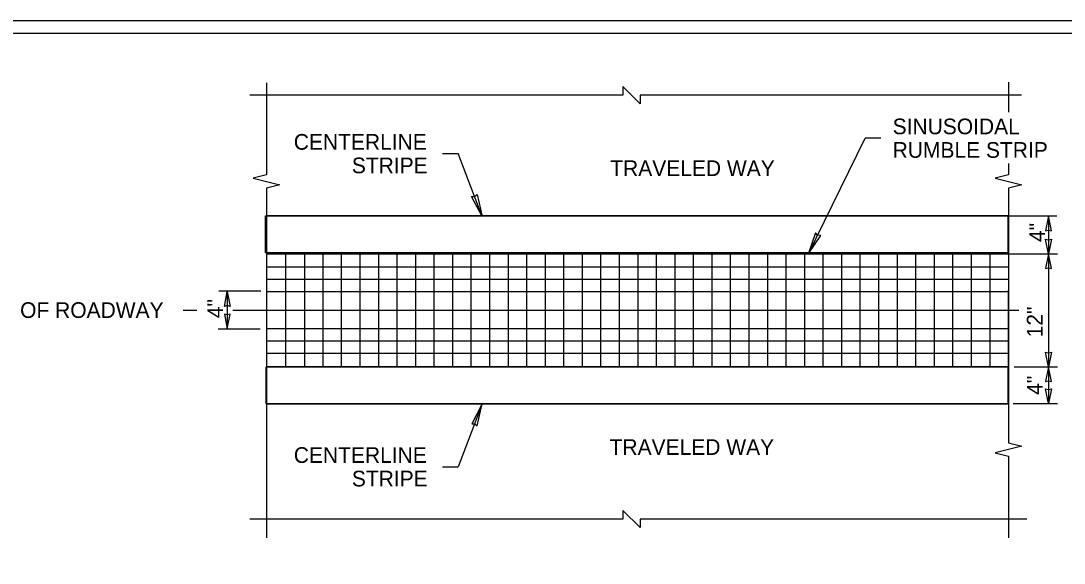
# Model space of a CAD drawing. Extents: x 100019.3 to 100035.8, y 99999.9 to 100024.4.
# Drawn here: x 100024.46 to 100029.77, y 100021.67 to 100024.44 of the extents above; entities that cross this region are included whole.
import ezdxf

# ---------------------------------------------------------------- set-up
doc = ezdxf.new("R2010")
doc.units = 0
for name, color, linetype in [('Level 10', 7, 'Continuous'), ('Level 14', 7, 'Continuous'), ('Level 15', 7, 'Continuous'), ('Level 16', 7, 'Continuous'), ('Level 18', 7, 'Continuous'), ('Level 20', 7, 'Continuous'), ('Level 22', 7, 'Continuous'), ('Level 45', 7, 'Continuous'), ('Level 50', 7, 'Continuous'), ('SH_GI_PlotLimits', 7, 'Continuous'), ('SH_GI_SheetBorder', 7, 'Continuous')]:
    doc.layers.add(name, color=color, linetype=linetype)

msp = doc.modelspace()

# ---------------------------------------------------------------- linework, layer by layer
at = {"layer": 'Level 10'}
for p, q in [((100025.8077, 100022.6793), (100025.8077, 100023.2455)), ((100025.9037, 100022.6793), (100025.9037, 100023.2455)), ((100025.9977, 100022.6793), (100025.9977, 100023.2455)), ((100026.0921, 100023.0648), (100026.0921, 100023.2455)), ((100026.1865, 100023.0648), (100026.1865, 100023.2455)), ((100026.2808, 100023.0648), (100026.2808, 100023.2455)), ((100026.3752, 100023.0648), (100026.3752, 100023.2455)), ((100026.4696, 100023.0648), (100026.4696, 100023.2455)), ((100026.564, 100023.0648), (100026.564, 100023.2455)), ((100026.6583, 100023.0648), (100026.6583, 100023.2455)), ((100026.7527, 100022.6793), (100026.7527, 100023.2455)), ((100026.8471, 100023.0648), (100026.8471, 100023.2455)), ((100026.9414, 100023.0648), (100026.9414, 100023.2455)), ((100027.0358, 100023.0648), (100027.0358, 100023.2455)), ((100027.1302, 100023.0648), (100027.1302, 100023.2455)), ((100027.2246, 100023.0648), (100027.2246, 100023.2455)), ((100027.3189, 100023.0648), (100027.3189, 100023.2455)), ((100027.4133, 100023.0648), (100027.4133, 100023.2455)), ((100027.5077, 100022.6793), (100027.5077, 100023.2455)), ((100027.602, 100023.0648), (100027.602, 100023.2455)), ((100027.6964, 100023.0648), (100027.6964, 100023.2455)), ((100027.7908, 100023.0648), (100027.7908, 100023.2455)), ((100027.8852, 100023.0648), (100027.8852, 100023.2455)), ((100027.9795, 100023.0648), (100027.9795, 100023.2455)), ((100028.0739, 100023.0648), (100028.0739, 100023.2455)), ((100028.1683, 100023.0648), (100028.1683, 100023.2455)), ((100028.2626, 100022.6793), (100028.2626, 100023.2455)), ((100028.357, 100023.0648), (100028.357, 100023.2455)), ((100028.4514, 100023.0648), (100028.4514, 100023.2455)), ((100028.5458, 100023.0648), (100028.5458, 100023.2455)), ((100028.6401, 100023.0648), (100028.6401, 100023.2455)), ((100028.7345, 100023.0648), (100028.7345, 100023.2455)), ((100028.8289, 100023.0648), (100028.8289, 100023.2455)), ((100028.9232, 100023.0648), (100028.9232, 100023.2455)), ((100029.0176, 100022.6793), (100029.0176, 100023.2455)), ((100029.112, 100023.0648), (100029.112, 100023.2455)), ((100029.2064, 100023.0648), (100029.2064, 100023.2455)), ((100029.3007, 100023.0648), (100029.3007, 100023.2455)), ((100029.3951, 100023.2455), (100029.3951, 100023.0648)), ((100026.0921, 100022.8492), (100026.0921, 100023.0648)), ((100026.1865, 100022.8492), (100026.1865, 100023.0648)), ((100026.2808, 100022.8492), (100026.2808, 100023.0648)), ((100026.3752, 100022.8492), (100026.3752, 100023.0648)), ((100026.4696, 100022.8492), (100026.4696, 100023.0648)), ((100026.564, 100022.8492), (100026.564, 100023.0648)), ((100026.6583, 100022.8492), (100026.6583, 100023.0648)), ((100026.8471, 100022.8492), (100026.8471, 100023.0648)), ((100026.9414, 100022.8492), (100026.9414, 100023.0648)), ((100027.0358, 100022.8492), (100027.0358, 100023.0648)), ((100027.1302, 100022.8492), (100027.1302, 100023.0648)), ((100027.2246, 100022.8492), (100027.2246, 100023.0648)), ((100027.3189, 100022.8492), (100027.3189, 100023.0648)), ((100027.4133, 100022.8492), (100027.4133, 100023.0648)), ((100027.602, 100022.8492), (100027.602, 100023.0648)), ((100027.6964, 100022.8492), (100027.6964, 100023.0648)), ((100027.7908, 100022.8492), (100027.7908, 100023.0648)), ((100027.8852, 100022.8492), (100027.8852, 100023.0648)), ((100027.9795, 100022.8492), (100027.9795, 100023.0648)), ((100028.0739, 100022.8492), (100028.0739, 100023.0648)), ((100028.1683, 100022.8492), (100028.1683, 100023.0648)), ((100028.357, 100022.8492), (100028.357, 100023.0648)), ((100028.4514, 100022.8492), (100028.4514, 100023.0648)), ((100028.5458, 100022.8492), (100028.5458, 100023.0648)), ((100028.6401, 100022.8492), (100028.6401, 100023.0648)), ((100028.7345, 100022.8492), (100028.7345, 100023.0648)), ((100028.8289, 100022.8492), (100028.8289, 100023.0648)), ((100028.9232, 100022.8492), (100028.9232, 100023.0648)), ((100029.112, 100022.8492), (100029.112, 100023.0648)), ((100029.2064, 100022.8492), (100029.2064, 100023.0648)), ((100029.3007, 100022.8492), (100029.3007, 100023.0648)), ((100029.3951, 100023.0648), (100029.3951, 100022.8492)), ((100029.4895, 100022.8492), (100029.4895, 100023.0648)), ((100026.0921, 100022.6793), (100026.0921, 100022.8492)), ((100026.1865, 100022.6793), (100026.1865, 100022.8492)), ((100026.2808, 100022.6793), (100026.2808, 100022.8492)), ((100026.3752, 100022.6793), (100026.3752, 100022.8492)), ((100026.4696, 100022.6793), (100026.4696, 100022.8492)), ((100026.564, 100022.6793), (100026.564, 100022.8492)), ((100026.6583, 100022.6793), (100026.6583, 100022.8492)), ((100026.8471, 100022.6793), (100026.8471, 100022.8492)), ((100026.9414, 100022.6793), (100026.9414, 100022.8492)), ((100027.0358, 100022.6793), (100027.0358, 100022.8492)), ((100027.1302, 100022.6793), (100027.1302, 100022.8492)), ((100027.2246, 100022.6793), (100027.2246, 100022.8492)), ((100027.3189, 100022.6793), (100027.3189, 100022.8492)), ((100027.4133, 100022.6793), (100027.4133, 100022.8492)), ((100027.602, 100022.6793), (100027.602, 100022.8492)), ((100027.6964, 100022.6793), (100027.6964, 100022.8492)), ((100027.7908, 100022.6793), (100027.7908, 100022.8492)), ((100027.8852, 100022.6793), (100027.8852, 100022.8492)), ((100027.9795, 100022.6793), (100027.9795, 100022.8492)), ((100028.0739, 100022.6793), (100028.0739, 100022.8492)), ((100028.1683, 100022.6793), (100028.1683, 100022.8492)), ((100028.357, 100022.6793), (100028.357, 100022.8492)), ((100028.4514, 100022.6793), (100028.4514, 100022.8492)), ((100028.5458, 100022.6793), (100028.5458, 100022.8492)), ((100028.6401, 100022.6793), (100028.6401, 100022.8492)), ((100028.7345, 100022.6793), (100028.7345, 100022.8492)), ((100028.8289, 100022.6793), (100028.8289, 100022.8492)), ((100028.9232, 100022.6793), (100028.9232, 100022.8492)), ((100029.112, 100022.6793), (100029.112, 100022.8492)), ((100029.2064, 100022.6793), (100029.2064, 100022.8492)), ((100029.3007, 100022.6793), (100029.3007, 100022.8492)), ((100029.3951, 100022.8492), (100029.3951, 100022.6793)), ((100029.4895, 100022.6793), (100029.4895, 100022.8492))]:
    msp.add_line(p, q, dxfattribs=at)
at = {"layer": 'Level 14'}
for p, q in [((100029.6934, 100023.443), (100029.6934, 100023.2498)), ((100025.5092, 100023.0578), (100025.5092, 100022.8659)), ((100029.6934, 100022.6738), (100029.6934, 100022.4866))]:
    msp.add_line(p, q, dxfattribs=at)
at = {"layer": 'Level 15'}
for p, q in [((100025.7093, 100024.1218), (100025.7093, 100023.6527)), ((100029.4895, 100024.1258), (100029.4895, 100023.9716)), ((100028.4683, 100023.2471), (100028.7595, 100023.8394)), ((100026.8077, 100023.4397), (100026.6855, 100023.7606)), ((100029.4895, 100023.7105), (100029.4895, 100023.6527)), ((100025.7093, 100023.5842), (100025.7093, 100023.4859)), ((100029.4895, 100023.5842), (100029.4895, 100023.4999)), ((100025.7093, 100023.4911), (100025.7093, 100022.5899)), ((100029.4895, 100023.5168), (100029.4895, 100023.0973)), ((100029.4883, 100023.443), (100029.7359, 100023.443)), ((100029.4923, 100023.2498), (100029.74, 100023.2498)), ((100029.6934, 100023.2498), (100029.6934, 100022.6738)), ((100029.4895, 100023.0973), (100029.4895, 100022.5899)), ((100025.6809, 100023.0591), (100025.4667, 100023.0591)), ((100025.6768, 100022.8659), (100025.4626, 100022.8659)), ((100029.5181, 100022.6738), (100029.74, 100022.6738)), ((100025.7091, 100022.5899), (100025.7091, 100021.803)), ((100029.4895, 100022.5899), (100029.4895, 100022.2868)), ((100026.8077, 100022.4851), (100026.6855, 100022.1643)), ((100029.5141, 100022.4866), (100029.74, 100022.4866)), ((100029.4895, 100022.2183), (100029.4895, 100021.803))]:
    msp.add_line(p, q, dxfattribs=at)
for points in [[(100029.5555, 100024.0584), (100027.6128, 100024.0584), (100027.6128, 100024.0146), (100027.5251, 100024.1023), (100027.5251, 100024.0584), (100025.6245, 100024.0584)], [(100025.7093, 100023.6527), (100025.6408, 100023.6355), (100025.7778, 100023.6013), (100025.7093, 100023.5842)], [(100029.4895, 100023.6527), (100029.421, 100023.6355), (100029.558, 100023.6013), (100029.4895, 100023.5842)], [(100029.4895, 100022.2868), (100029.558, 100022.2696), (100029.421, 100022.2354), (100029.4895, 100022.2183)], [(100029.5822, 100021.8982), (100027.6128, 100021.8982), (100027.6128, 100021.8543), (100027.5251, 100021.942), (100027.5251, 100021.8982), (100025.6245, 100021.8982)]]:
    msp.add_lwpolyline(points, dxfattribs=at)
at = {"layer": 'Level 18'}
for p, q in [((100029.4883, 100023.2542), (100029.4883, 100023.443)), ((100029.4883, 100022.4851), (100029.4883, 100022.6738))]:
    msp.add_line(p, q, dxfattribs=at)
for points in [[(100025.7034, 100023.443), (100029.4883, 100023.443), (100029.4883, 100023.2542), (100025.7034, 100023.2542)], [(100025.7079, 100022.6738), (100029.4903, 100022.6738), (100029.4903, 100022.4851), (100025.7079, 100022.4851)]]:
    msp.add_lwpolyline(points, close=True, dxfattribs=at)
for points in [[(100029.4883, 100023.443), (100029.3911, 100023.443), (100029.2967, 100023.443), (100029.2023, 100023.443), (100029.1079, 100023.443), (100029.0136, 100023.443), (100028.9192, 100023.443), (100028.8248, 100023.443), (100028.7305, 100023.443), (100028.6361, 100023.443), (100028.5417, 100023.443), (100028.4473, 100023.443), (100028.353, 100023.443), (100025.7079, 100023.443)], [(100025.7079, 100023.2542), (100028.353, 100023.2542), (100028.4473, 100023.2542), (100028.5417, 100023.2542), (100028.6361, 100023.2542), (100028.7305, 100023.2542), (100028.8248, 100023.2542), (100028.9192, 100023.2542), (100029.0136, 100023.2542), (100029.1079, 100023.2542), (100029.2023, 100023.2542), (100029.2967, 100023.2542), (100029.3911, 100023.2542), (100029.4883, 100023.2542)], [(100029.4883, 100022.6738), (100029.3911, 100022.6738), (100029.2967, 100022.6738), (100029.2023, 100022.6738), (100029.1079, 100022.6738), (100029.0136, 100022.6738), (100028.9192, 100022.6738), (100028.8248, 100022.6738), (100028.7305, 100022.6738), (100028.6361, 100022.6738), (100028.5417, 100022.6738), (100028.4473, 100022.6738), (100028.353, 100022.6738), (100025.7079, 100022.6738)], [(100025.7079, 100022.4851), (100028.353, 100022.4851), (100028.4473, 100022.4851), (100028.5417, 100022.4851), (100028.6361, 100022.4851), (100028.7305, 100022.4851), (100028.8248, 100022.4851), (100028.9192, 100022.4851), (100029.0136, 100022.4851), (100029.1079, 100022.4851), (100029.2023, 100022.4851), (100029.2967, 100022.4851), (100029.3911, 100022.4851), (100029.4883, 100022.4851)]]:
    msp.add_lwpolyline(points, dxfattribs=at)
at = {"layer": 'Level 20'}
for p, q in [((100028.8392, 100023.8394), (100028.7595, 100023.8394)), ((100026.6055, 100023.7606), (100026.6855, 100023.7606)), ((100026.6055, 100022.1643), (100026.6855, 100022.1643))]:
    msp.add_line(p, q, dxfattribs=at)
for points in [[(100026.8077, 100023.4397), (100026.7538, 100023.5415), (100026.7696, 100023.5417), (100026.7818, 100023.5519)], [(100029.6934, 100023.443), (100029.6786, 100023.3675), (100029.6934, 100023.371), (100029.7082, 100023.3675)], [(100028.4691, 100023.2482), (100028.5328, 100023.3441), (100028.517, 100023.3459), (100028.506, 100023.3573)], [(100029.6934, 100023.2498), (100029.6786, 100023.3253), (100029.6934, 100023.3218), (100029.7082, 100023.3253)], [(100029.6934, 100023.2498), (100029.6786, 100023.1744), (100029.6934, 100023.1779), (100029.7082, 100023.1744)], [(100025.5092, 100023.0578), (100025.524, 100022.9823), (100025.5092, 100022.9858), (100025.4944, 100022.9823)], [(100025.5092, 100022.8675), (100025.524, 100022.943), (100025.5092, 100022.9395), (100025.4944, 100022.943)], [(100029.6934, 100022.6738), (100029.6786, 100022.7493), (100029.6934, 100022.7458), (100029.7082, 100022.7493)], [(100029.6934, 100022.6738), (100029.6786, 100022.5984), (100029.6934, 100022.6019), (100029.7082, 100022.5984)], [(100029.6934, 100022.4866), (100029.6786, 100022.5621), (100029.6934, 100022.5586), (100029.7082, 100022.5621)], [(100026.8077, 100022.4851), (100026.7546, 100022.383), (100026.7704, 100022.3828), (100026.7826, 100022.3727)]]:
    msp.add_lwpolyline(points, close=True, dxfattribs=at)
at = {"layer": 'Level 22'}
for p, q in [((100025.3546, 100022.9618), (100025.2847, 100022.9618)), ((100029.543, 100022.9618), (100025.5378, 100022.9618))]:
    msp.add_line(p, q, dxfattribs=at)
at = {"layer": 'Level 45'}
for p, q in [((100025.7093, 100023.443), (100029.4895, 100023.443)), ((100025.7081, 100022.4851), (100029.4883, 100022.4851))]:
    msp.add_line(p, q, dxfattribs=at)
at = {"layer": 'Level 50'}
for p, q in [((100025.7093, 100023.2498), (100029.4895, 100023.2498)), ((100025.9969, 100023.0568), (100025.9969, 100023.0568)), ((100025.9969, 100023.0568), (100025.9969, 100023.0568)), ((100025.9977, 100023.0568), (100025.9977, 100023.0568)), ((100028.2626, 100023.0568), (100028.2626, 100023.0568)), ((100028.2626, 100023.0568), (100028.2626, 100023.0568)), ((100025.9969, 100022.9939), (100025.9969, 100022.9939)), ((100025.9969, 100022.9939), (100025.9969, 100022.9939)), ((100025.9977, 100022.9939), (100025.9977, 100022.9939)), ((100028.2626, 100022.9939), (100028.2626, 100022.9939)), ((100028.2626, 100022.9939), (100028.2626, 100022.9939)), ((100025.9969, 100022.931), (100025.9969, 100022.931)), ((100025.9969, 100022.931), (100025.9969, 100022.931)), ((100025.9977, 100022.931), (100025.9977, 100022.931)), ((100028.2626, 100022.931), (100028.2626, 100022.931)), ((100028.2626, 100022.931), (100028.2626, 100022.931)), ((100025.9969, 100022.868), (100025.9969, 100022.868)), ((100025.9977, 100022.868), (100025.9977, 100022.868)), ((100028.2626, 100022.868), (100028.2626, 100022.868)), ((100028.2626, 100022.868), (100028.2626, 100022.868)), ((100029.4895, 100022.6738), (100025.7093, 100022.6738))]:
    msp.add_line(p, q, dxfattribs=at)
for points in [[(100027.1302, 100023.1826), (100027.0358, 100023.1826), (100026.9414, 100023.1826), (100026.8471, 100023.1826), (100026.7527, 100023.1826), (100026.6583, 100023.1826), (100026.564, 100023.1826), (100026.4696, 100023.1826), (100026.3752, 100023.1826), (100026.2808, 100023.1826), (100026.1865, 100023.1826), (100026.0921, 100023.1826), (100025.7093, 100023.1826)], [(100028.2626, 100023.1826), (100028.1683, 100023.1826), (100028.0739, 100023.1826), (100027.9795, 100023.1826), (100027.8852, 100023.1826), (100027.7908, 100023.1826), (100027.6964, 100023.1826), (100027.602, 100023.1826), (100027.5077, 100023.1826), (100027.4133, 100023.1826), (100027.3189, 100023.1826), (100027.2246, 100023.1826), (100027.1302, 100023.1826)], [(100029.4895, 100023.1826), (100029.3951, 100023.1826), (100029.3007, 100023.1826), (100029.2064, 100023.1826), (100029.112, 100023.1826), (100029.0176, 100023.1826), (100028.9232, 100023.1826), (100028.8289, 100023.1826), (100028.7345, 100023.1826), (100028.6401, 100023.1826), (100028.5458, 100023.1826), (100028.4514, 100023.1826), (100028.357, 100023.1826), (100028.2626, 100023.1826)], [(100027.1302, 100023.1197), (100027.0358, 100023.1197), (100026.9414, 100023.1197), (100026.8471, 100023.1197), (100026.7527, 100023.1197), (100026.6583, 100023.1197), (100026.564, 100023.1197), (100026.4696, 100023.1197), (100026.3752, 100023.1197), (100026.2808, 100023.1197), (100026.1865, 100023.1197), (100026.0921, 100023.1197), (100025.7093, 100023.1197)], [(100028.2626, 100023.1197), (100028.1683, 100023.1197), (100028.0739, 100023.1197), (100027.9795, 100023.1197), (100027.8852, 100023.1197), (100027.7908, 100023.1197), (100027.6964, 100023.1197), (100027.602, 100023.1197), (100027.5077, 100023.1197), (100027.4133, 100023.1197), (100027.3189, 100023.1197), (100027.2246, 100023.1197), (100027.1302, 100023.1197)], [(100029.4895, 100023.1197), (100029.3951, 100023.1197), (100029.3007, 100023.1197), (100029.2064, 100023.1197), (100029.112, 100023.1197), (100029.0176, 100023.1197), (100028.9232, 100023.1197), (100028.8289, 100023.1197), (100028.7345, 100023.1197), (100028.6401, 100023.1197), (100028.5458, 100023.1197), (100028.4514, 100023.1197), (100028.357, 100023.1197), (100028.2626, 100023.1197)], [(100027.1302, 100023.0568), (100027.0358, 100023.0568), (100026.9414, 100023.0568), (100026.8471, 100023.0568), (100026.7527, 100023.0568), (100026.6583, 100023.0568), (100026.564, 100023.0568), (100026.4696, 100023.0568), (100026.3752, 100023.0568), (100026.2808, 100023.0568), (100026.1865, 100023.0568), (100026.0921, 100023.0568), (100025.7093, 100023.0568)], [(100028.2626, 100023.0568), (100028.1683, 100023.0568), (100028.0739, 100023.0568), (100027.9795, 100023.0568), (100027.8852, 100023.0568), (100027.7908, 100023.0568), (100027.6964, 100023.0568), (100027.602, 100023.0568), (100027.5077, 100023.0568), (100027.4133, 100023.0568), (100027.3189, 100023.0568), (100027.2246, 100023.0568), (100027.1302, 100023.0568)], [(100029.4895, 100023.0568), (100029.3951, 100023.0568), (100029.3007, 100023.0568), (100029.2064, 100023.0568), (100029.112, 100023.0568), (100029.0176, 100023.0568), (100028.9232, 100023.0568), (100028.8289, 100023.0568), (100028.7345, 100023.0568), (100028.6401, 100023.0568), (100028.5458, 100023.0568), (100028.4514, 100023.0568), (100028.357, 100023.0568), (100028.2626, 100023.0568)], [(100027.1302, 100022.868), (100027.0358, 100022.868), (100026.9414, 100022.868), (100026.8471, 100022.868), (100026.7527, 100022.868), (100026.6583, 100022.868), (100026.564, 100022.868), (100026.4696, 100022.868), (100026.3752, 100022.868), (100026.2808, 100022.868), (100026.1865, 100022.868), (100026.0921, 100022.868), (100025.7093, 100022.868)], [(100028.2626, 100022.868), (100028.1683, 100022.868), (100028.0739, 100022.868), (100027.9795, 100022.868), (100027.8852, 100022.868), (100027.7908, 100022.868), (100027.6964, 100022.868), (100027.602, 100022.868), (100027.5077, 100022.868), (100027.4133, 100022.868), (100027.3189, 100022.868), (100027.2246, 100022.868), (100027.1302, 100022.868)], [(100029.4895, 100022.868), (100029.3951, 100022.868), (100029.3007, 100022.868), (100029.2064, 100022.868), (100029.112, 100022.868), (100029.0176, 100022.868), (100028.9232, 100022.868), (100028.8289, 100022.868), (100028.7345, 100022.868), (100028.6401, 100022.868), (100028.5458, 100022.868), (100028.4514, 100022.868), (100028.357, 100022.868), (100028.2626, 100022.868)], [(100027.1302, 100022.8051), (100027.0358, 100022.8051), (100026.9414, 100022.8051), (100026.8471, 100022.8051), (100026.7527, 100022.8051), (100026.6583, 100022.8051), (100026.564, 100022.8051), (100026.4696, 100022.8051), (100026.3752, 100022.8051), (100026.2808, 100022.8051), (100026.1865, 100022.8051), (100026.0921, 100022.8051), (100025.7093, 100022.8051)], [(100028.2626, 100022.8051), (100028.1683, 100022.8051), (100028.0739, 100022.8051), (100027.9795, 100022.8051), (100027.8852, 100022.8051), (100027.7908, 100022.8051), (100027.6964, 100022.8051), (100027.602, 100022.8051), (100027.5077, 100022.8051), (100027.4133, 100022.8051), (100027.3189, 100022.8051), (100027.2246, 100022.8051), (100027.1302, 100022.8051)], [(100029.4895, 100022.8051), (100029.3951, 100022.8051), (100029.3007, 100022.8051), (100029.2064, 100022.8051), (100029.112, 100022.8051), (100029.0176, 100022.8051), (100028.9232, 100022.8051), (100028.8289, 100022.8051), (100028.7345, 100022.8051), (100028.6401, 100022.8051), (100028.5458, 100022.8051), (100028.4514, 100022.8051), (100028.357, 100022.8051), (100028.2626, 100022.8051)], [(100027.1302, 100022.7422), (100027.0358, 100022.7422), (100026.9414, 100022.7422), (100026.8471, 100022.7422), (100026.7527, 100022.7422), (100026.6583, 100022.7422), (100026.564, 100022.7422), (100026.4696, 100022.7422), (100026.3752, 100022.7422), (100026.2808, 100022.7422), (100026.1865, 100022.7422), (100026.0921, 100022.7422), (100025.7093, 100022.7422)], [(100028.2626, 100022.7422), (100028.1683, 100022.7422), (100028.0739, 100022.7422), (100027.9795, 100022.7422), (100027.8852, 100022.7422), (100027.7908, 100022.7422), (100027.6964, 100022.7422), (100027.602, 100022.7422), (100027.5077, 100022.7422), (100027.4133, 100022.7422), (100027.3189, 100022.7422), (100027.2246, 100022.7422), (100027.1302, 100022.7422)], [(100029.4895, 100022.7422), (100029.3951, 100022.7422), (100029.3007, 100022.7422), (100029.2064, 100022.7422), (100029.112, 100022.7422), (100029.0176, 100022.7422), (100028.9232, 100022.7422), (100028.8289, 100022.7422), (100028.7345, 100022.7422), (100028.6401, 100022.7422), (100028.5458, 100022.7422), (100028.4514, 100022.7422), (100028.357, 100022.7422), (100028.2626, 100022.7422)]]:
    msp.add_lwpolyline(points, dxfattribs=at)
at = {"layer": 'SH_GI_PlotLimits'}
msp.add_lwpolyline([(100019.3125, 100013.9375), (100035.8125, 100013.9375), (100035.8125, 100024.4375), (100019.3125, 100024.4375)], close=True, dxfattribs=at)
at = {"layer": 'SH_GI_SheetBorder'}
msp.add_line((100020, 100024.375), (100035.75, 100024.375), dxfattribs=at)
msp.add_line((100020, 100024.375), (100035.75, 100024.375), dxfattribs=at)

# ---------------------------------------------------------------- texts
at = {"layer": 'Level 16'}
msp.add_text('WSDOT HQ Design Office', height=0.7, rotation=30.7778, dxfattribs=at).set_placement((100022.8123, 100016.4746))
at = {"layer": 'Level 20'}
for s, p in [('SINUSOIDAL ', (100028.8992, 100023.8594)), ('CENTERLINE ', (100025.8482, 100023.7806)), ('RUMBLE STRIP', (100028.8992, 100023.7394)), ('STRIPE', (100026.144, 100023.6606)), ('TRAVELED WAY', (100027.4605, 100023.6465)), ('TRAVELED WAY', (100027.4573, 100022.2251)), ('CENTERLINE ', (100025.8482, 100022.1843)), ('STRIPE', (100026.144, 100022.0643))]:
    msp.add_text(s, height=0.08, dxfattribs=at).set_placement(p)
for s, rotation, p in [('4"', 90, (100029.675, 100023.3102)), ('4"', 90, (100025.4878, 100022.9218)), ('OF ROADWAY', 360, (100024.4539, 100022.9231)), ('12"', 90, (100029.663, 100022.8244)), ('4"', 90, (100029.663, 100022.531))]:
    msp.add_text(s, height=0.08, rotation=rotation, dxfattribs=at).set_placement(p)

doc.saveas('drawing.dxf')
